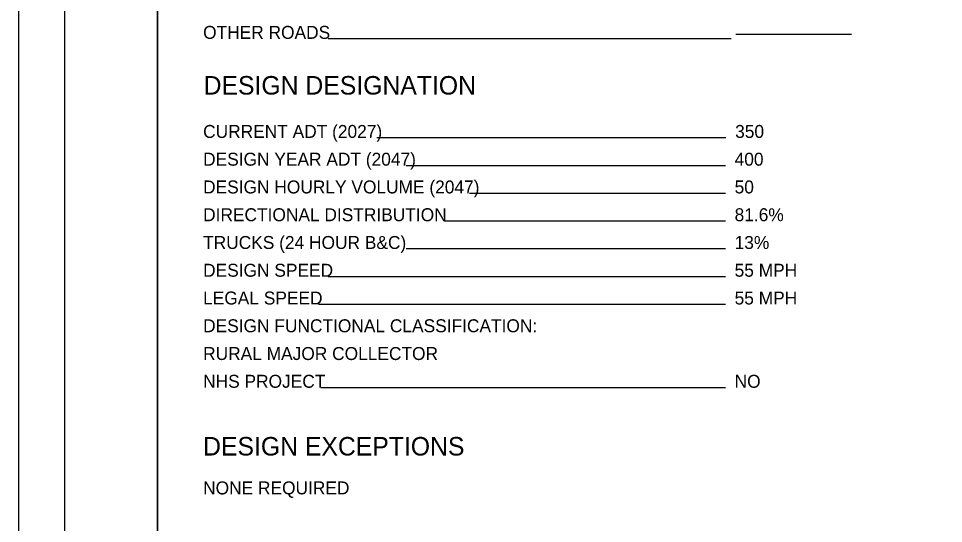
# Model space of a CAD drawing. Extents: x 0 to 34, y 0 to 22.
# Drawn here: x 0 to 9.99, y 5.64 to 11.1 of the extents above; entities that cross this region are included whole.
import ezdxf

# ---------------------------------------------------------------- set-up
doc = ezdxf.new("R2010")
doc.units = 0
for name, color, linetype in [('SH_Border', 7, 'Continuous'), ('SH_Cut_Line', 7, 'Continuous'), ('SH_Data', 7, 'Continuous'), ('SH_Text', 7, 'Continuous')]:
    doc.layers.add(name, color=color, linetype=linetype)

msp = doc.modelspace()

# ---------------------------------------------------------------- linework, layer by layer
at = {"layer": 'SH_Border'}
for points in [[(0.5, 21.5), (1.5, 21.5), (1.5, 0.5), (0.5, 0.5)], [(1.5, 21.5), (33.5, 21.5), (33.5, 0.5), (1.5, 0.5)]]:
    msp.add_lwpolyline(points, close=True, dxfattribs=at)
at = {"layer": 'SH_Cut_Line'}
msp.add_lwpolyline([(0, 0), (34, 0), (34, 22), (0, 22)], close=True, dxfattribs=at)
at = {"layer": 'SH_Data'}
for p, q in [((9, 10.9223), (7.75, 10.9223)), ((7.7, 10.8767), (3.3471, 10.8767)), ((7.6424, 9.8062), (3.871, 9.8062)), ((7.6368, 9.5062), (4.1885, 9.5062)), ((7.6368, 9.2062), (4.8723, 9.2062)), ((7.6368, 8.9062), (4.6037, 8.9062)), ((7.6368, 8.6062), (4.1885, 8.6062)), ((7.6368, 8.3062), (3.346, 8.3062)), ((7.6368, 8.0062), (3.2422, 8.0062)), ((7.6368, 7.1062), (3.2669, 7.1062))]:
    msp.add_line(p, q, dxfattribs=at)

# ---------------------------------------------------------------- texts
msp.add_text('DESIGN DESIGNATION', height=0.2, dxfattribs=at).set_placement((2, 10.2747))
at = {"layer": 'SH_Text'}
for s, height, p in [('OTHER ROADS', 0.14, (1.9944, 10.8767)), ('CURRENT ADT (2027)', 0.14, (1.9944, 9.8062)), ('350', 0.14, (7.7424, 9.8062)), ('DESIGN YEAR ADT (2047)', 0.14, (1.9944, 9.5062)), ('400', 0.14, (7.7368, 9.5062)), ('DESIGN HOURLY VOLUME (2047)', 0.14, (1.9944, 9.2062)), ('50', 0.14, (7.7368, 9.2062)), ('DIRECTIONAL DISTRIBUTION', 0.14, (1.9944, 8.9062)), ('81.6%', 0.14, (7.7368, 8.9062)), ('TRUCKS (24 HOUR B&C)', 0.14, (1.9944, 8.6062)), ('13%', 0.14, (7.7368, 8.6062)), ('DESIGN SPEED', 0.14, (1.9944, 8.3062)), ('55 MPH', 0.14, (7.7368, 8.3062)), ('LEGAL SPEED', 0.14, (1.9944, 8.0062)), ('55 MPH', 0.14, (7.7368, 8.0062)), ('DESIGN FUNCTIONAL CLASSIFICATION:', 0.14, (1.9944, 7.7062)), ('RURAL MAJOR COLLECTOR', 0.14, (1.9944, 7.4062)), ('NHS PROJECT', 0.14, (1.9944, 7.1062)), ('NO', 0.14, (7.7368, 7.1062)), ('DESIGN EXCEPTIONS', 0.2, (1.9944, 6.3744)), ('NONE REQUIRED', 0.14, (1.9944, 5.9544))]:
    msp.add_text(s, height=height, dxfattribs=at).set_placement(p)

doc.saveas('drawing.dxf')
